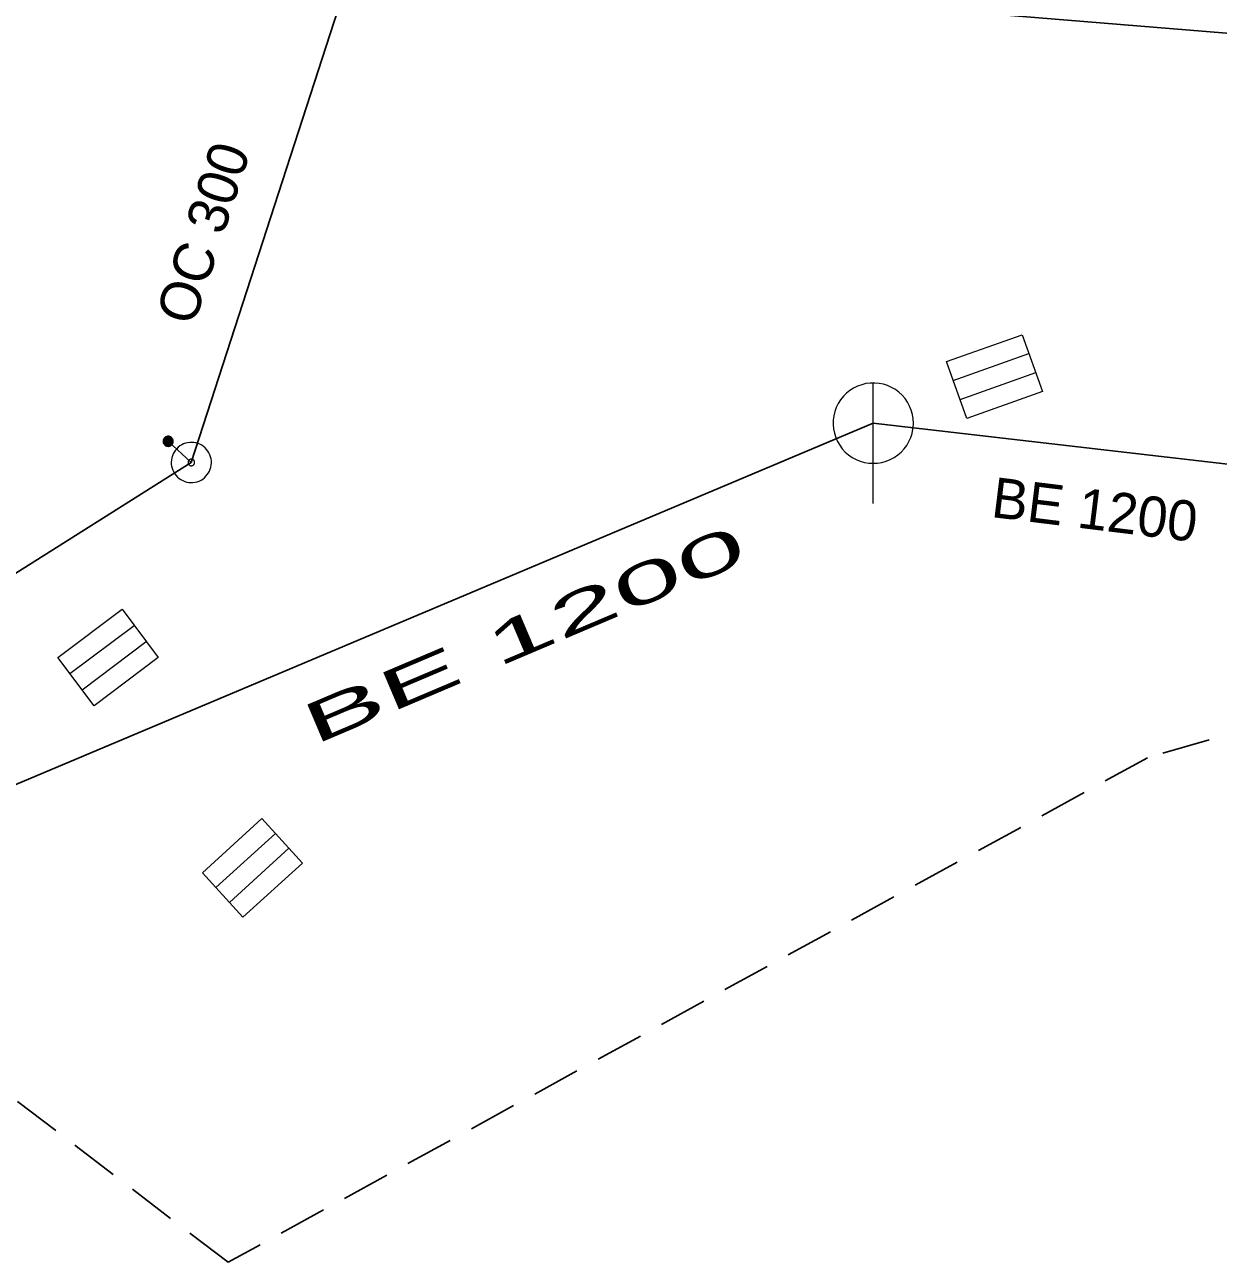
# Model space of a CAD drawing. Extents: x -725643 to -725418, y -978375 to -978221.
# Drawn here: x -725556.54 to -725526.82, y -978371.93 to -978341.11 of the extents above; entities that cross this region are included whole.
import ezdxf

# ---------------------------------------------------------------- set-up
doc = ezdxf.new("R2010")
doc.units = 0
doc.header["$LTSCALE"] = 0.4
doc.linetypes.add('MEDIUM_DASHED', pattern=[4.5, 3, -1.5])
doc.layers.add('1', color=7, linetype='Continuous')
for name, color, linetype, lineweight in [('14', 7, 'Continuous', 25), ('17', 7, 'Continuous', 25), ('22', 7, 'Continuous', 13), ('47', 7, 'Continuous', 13), ('63', 7, 'MEDIUM_DASHED', 25), ('9', 7, 'Continuous', 13)]:
    doc.layers.add(name, color=color, linetype=linetype, lineweight=lineweight)

msp = doc.modelspace()

# ---------------------------------------------------------------- linework, layer by layer
at = {"layer": '14'}
msp.add_line((-725535.414, -978351.036), (-725558.362, -978360.71), dxfattribs=at)
at = {"layer": '14', "lineweight": 13}
msp.add_line((-725552.39, -978352.015), (-725552.967, -978351.487), dxfattribs=at)
at = {"layer": '14'}
msp.add_lwpolyline([(-725503.472, -978351.493), (-725519.776, -978352.842), (-725535.414, -978351.036)], dxfattribs=at)
at = {"layer": '17'}
for p, q in [((-725548.553, -978340.172), (-725552.39, -978352.015)), ((-725552.39, -978352.015), (-725564.342, -978359.539))]:
    msp.add_line(p, q, dxfattribs=at)
msp.add_lwpolyline([(-725516.432, -978342.059), (-725524.989, -978341.46), (-725545.003, -978339.812), (-725548.553, -978340.172), (-725550.989, -978339.387)], dxfattribs=at)
at = {"layer": '22'}
for p, q in [((-725533.42, -978349.974), (-725531.536, -978349.303)), ((-725535.414, -978353.035), (-725535.413, -978350.035)), ((-725533.252, -978350.445), (-725531.368, -978349.775)), ((-725555.412, -978357.273), (-725553.813, -978356.071)), ((-725555.111, -978357.673), (-725553.513, -978356.471)), ((-725551.777, -978362.598), (-725550.298, -978361.252)), ((-725551.44, -978362.968), (-725549.961, -978361.622))]:
    msp.add_line(p, q, dxfattribs=at)
for points in [[(-725533.588, -978349.502), (-725531.703, -978348.832), (-725531.201, -978350.246), (-725533.085, -978350.916)], [(-725534.414, -978351.035), (-725534.419, -978350.926), (-725534.437, -978350.818), (-725534.467, -978350.712), (-725534.507, -978350.611), (-725534.559, -978350.514), (-725534.621, -978350.424), (-725534.693, -978350.341), (-725534.773, -978350.267), (-725534.861, -978350.201), (-725534.955, -978350.146), (-725535.055, -978350.101), (-725535.16, -978350.068), (-725535.267, -978350.046), (-725535.376, -978350.036), (-725535.486, -978350.038), (-725535.594, -978350.052), (-725535.701, -978350.077), (-725535.804, -978350.114), (-725535.902, -978350.163), (-725535.994, -978350.221), (-725536.08, -978350.29), (-725536.157, -978350.367), (-725536.226, -978350.453), (-725536.285, -978350.545), (-725536.333, -978350.643), (-725536.37, -978350.746), (-725536.396, -978350.853), (-725536.41, -978350.961), (-725536.413, -978351.071), (-725536.403, -978351.18), (-725536.382, -978351.287), (-725536.348, -978351.391), (-725536.304, -978351.491), (-725536.249, -978351.586), (-725536.183, -978351.674), (-725536.109, -978351.754), (-725536.026, -978351.826), (-725535.936, -978351.888), (-725535.84, -978351.94), (-725535.738, -978351.981), (-725535.633, -978352.011), (-725535.525, -978352.029), (-725535.415, -978352.035), (-725535.306, -978352.029), (-725535.198, -978352.011), (-725535.093, -978351.982), (-725534.991, -978351.941), (-725534.894, -978351.889), (-725534.804, -978351.827), (-725534.721, -978351.756), (-725534.646, -978351.676), (-725534.581, -978351.588), (-725534.525, -978351.494), (-725534.481, -978351.394), (-725534.447, -978351.29), (-725534.425, -978351.182), (-725534.415, -978351.073)], [(-725555.712, -978356.874), (-725554.114, -978355.671), (-725553.212, -978356.87), (-725554.81, -978358.072)], [(-725552.113, -978362.229), (-725550.635, -978360.882), (-725549.625, -978361.991), (-725551.104, -978363.338)]]:
    msp.add_lwpolyline(points, close=True, dxfattribs=at)
at = {"layer": '47'}
for points in [[(-725551.89, -978352.026), (-725551.891, -978351.974), (-725551.898, -978351.921), (-725551.911, -978351.871), (-725551.928, -978351.822), (-725551.951, -978351.774), (-725551.979, -978351.73), (-725552.011, -978351.689), (-725552.047, -978351.651), (-725552.087, -978351.617), (-725552.13, -978351.587), (-725552.176, -978351.562), (-725552.225, -978351.543), (-725552.275, -978351.528), (-725552.326, -978351.519), (-725552.378, -978351.515), (-725552.43, -978351.516), (-725552.483, -978351.523), (-725552.534, -978351.536), (-725552.582, -978351.553), (-725552.63, -978351.576), (-725552.674, -978351.604), (-725552.716, -978351.636), (-725552.754, -978351.672), (-725552.788, -978351.712), (-725552.817, -978351.755), (-725552.842, -978351.801), (-725552.862, -978351.85), (-725552.876, -978351.9), (-725552.885, -978351.951), (-725552.889, -978352.003), (-725552.888, -978352.055), (-725552.881, -978352.108), (-725552.869, -978352.159), (-725552.851, -978352.207), (-725552.828, -978352.255), (-725552.801, -978352.299), (-725552.769, -978352.341), (-725552.733, -978352.379), (-725552.692, -978352.413), (-725552.649, -978352.442), (-725552.603, -978352.467), (-725552.555, -978352.487), (-725552.504, -978352.501), (-725552.453, -978352.51), (-725552.401, -978352.514), (-725552.349, -978352.513), (-725552.296, -978352.506), (-725552.246, -978352.494), (-725552.197, -978352.476), (-725552.149, -978352.453), (-725552.105, -978352.426), (-725552.064, -978352.394), (-725552.026, -978352.358), (-725551.992, -978352.317), (-725551.962, -978352.274), (-725551.937, -978352.228), (-725551.918, -978352.18), (-725551.903, -978352.129), (-725551.894, -978352.078)], [(-725552.308, -978352.016), (-725552.307, -978352.007), (-725552.309, -978351.999), (-725552.311, -978351.991), (-725552.314, -978351.983), (-725552.318, -978351.975), (-725552.322, -978351.968), (-725552.327, -978351.961), (-725552.333, -978351.955), (-725552.34, -978351.95), (-725552.347, -978351.944), (-725552.355, -978351.94), (-725552.363, -978351.937), (-725552.371, -978351.935), (-725552.379, -978351.933), (-725552.388, -978351.933), (-725552.397, -978351.932), (-725552.405, -978351.934), (-725552.413, -978351.936), (-725552.421, -978351.939), (-725552.429, -978351.943), (-725552.436, -978351.947), (-725552.443, -978351.952), (-725552.449, -978351.958), (-725552.455, -978351.965), (-725552.46, -978351.972), (-725552.464, -978351.98), (-725552.467, -978351.988), (-725552.469, -978351.996), (-725552.471, -978352.004), (-725552.471, -978352.013), (-725552.472, -978352.022), (-725552.47, -978352.03), (-725552.468, -978352.038), (-725552.465, -978352.046), (-725552.461, -978352.054), (-725552.458, -978352.061), (-725552.452, -978352.068), (-725552.446, -978352.074), (-725552.439, -978352.08), (-725552.432, -978352.085), (-725552.424, -978352.089), (-725552.416, -978352.092), (-725552.408, -978352.094), (-725552.4, -978352.096), (-725552.391, -978352.096), (-725552.382, -978352.097), (-725552.374, -978352.095), (-725552.366, -978352.093), (-725552.358, -978352.09), (-725552.35, -978352.086), (-725552.343, -978352.083), (-725552.336, -978352.077), (-725552.33, -978352.071), (-725552.325, -978352.064), (-725552.319, -978352.057), (-725552.315, -978352.049), (-725552.312, -978352.041), (-725552.31, -978352.033), (-725552.308, -978352.025)]]:
    msp.add_lwpolyline(points, close=True, dxfattribs=at)
at = {"layer": '63'}
msp.add_lwpolyline([(-725440.663, -978348.762), (-725504.582, -978352.39), (-725504.582, -978352.39), (-725528.587, -978359.368), (-725528.587, -978359.368), (-725551.474, -978371.929), (-725551.474, -978371.929), (-725566.826, -978360.206), (-725566.826, -978360.206), (-725557.894, -978328.944), (-725533.89, -978332.573), (-725533.89, -978332.573), (-725529.424, -978311.918), (-725529.424, -978311.918), (-725514.351, -978316.105), (-725514.351, -978316.105), (-725517.422, -978329.502), (-725517.422, -978329.502), (-725504.582, -978332.573), (-725504.582, -978332.573), (-725495.092, -978321.408)], dxfattribs=at)
at = {"layer": '9'}
for points in [[(-725553.093, -978351.487), (-725553.093, -978351.5), (-725553.09, -978351.513), (-725553.088, -978351.526), (-725553.083, -978351.538), (-725553.076, -978351.55), (-725553.07, -978351.561), (-725553.061, -978351.571), (-725553.051, -978351.581), (-725553.041, -978351.589), (-725553.031, -978351.596), (-725553.019, -978351.602), (-725553.007, -978351.607), (-725552.994, -978351.61), (-725552.98, -978351.612), (-725552.968, -978351.614), (-725552.955, -978351.613), (-725552.941, -978351.611), (-725552.929, -978351.608), (-725552.916, -978351.603), (-725552.904, -978351.597), (-725552.894, -978351.59), (-725552.884, -978351.582), (-725552.874, -978351.572), (-725552.865, -978351.562), (-725552.858, -978351.551), (-725552.853, -978351.539), (-725552.848, -978351.527), (-725552.845, -978351.514), (-725552.843, -978351.501), (-725552.84, -978351.488), (-725552.842, -978351.475), (-725552.843, -978351.462), (-725552.847, -978351.449), (-725552.852, -978351.437), (-725552.857, -978351.425), (-725552.865, -978351.414), (-725552.872, -978351.404), (-725552.882, -978351.394), (-725552.892, -978351.386), (-725552.904, -978351.379), (-725552.916, -978351.373), (-725552.928, -978351.368), (-725552.941, -978351.365), (-725552.953, -978351.363), (-725552.967, -978351.362), (-725552.98, -978351.362), (-725552.992, -978351.364), (-725553.005, -978351.367), (-725553.017, -978351.372), (-725553.029, -978351.378), (-725553.041, -978351.385), (-725553.051, -978351.393), (-725553.061, -978351.403), (-725553.068, -978351.413), (-725553.076, -978351.424), (-725553.081, -978351.436), (-725553.087, -978351.448), (-725553.09, -978351.461), (-725553.092, -978351.474)], [(-725553.073, -978351.487), (-725553.073, -978351.498), (-725553.071, -978351.509), (-725553.068, -978351.52), (-725553.065, -978351.53), (-725553.059, -978351.54), (-725553.054, -978351.549), (-725553.046, -978351.558), (-725553.039, -978351.566), (-725553.029, -978351.573), (-725553.021, -978351.579), (-725553.011, -978351.584), (-725553, -978351.588), (-725552.99, -978351.591), (-725552.978, -978351.594), (-725552.968, -978351.594), (-725552.956, -978351.594), (-725552.946, -978351.592), (-725552.934, -978351.589), (-725552.924, -978351.585), (-725552.914, -978351.58), (-725552.906, -978351.574), (-725552.897, -978351.567), (-725552.889, -978351.559), (-725552.882, -978351.55), (-725552.875, -978351.541), (-725552.87, -978351.531), (-725552.867, -978351.521), (-725552.864, -978351.51), (-725552.862, -978351.499), (-725552.86, -978351.488), (-725552.86, -978351.477), (-725552.862, -978351.466), (-725552.865, -978351.455), (-725552.87, -978351.445), (-725552.875, -978351.435), (-725552.88, -978351.426), (-725552.887, -978351.417), (-725552.896, -978351.409), (-725552.904, -978351.402), (-725552.914, -978351.396), (-725552.924, -978351.391), (-725552.933, -978351.387), (-725552.945, -978351.384), (-725552.955, -978351.382), (-725552.967, -978351.382), (-725552.978, -978351.381), (-725552.989, -978351.383), (-725553, -978351.386), (-725553.009, -978351.39), (-725553.019, -978351.395), (-725553.029, -978351.401), (-725553.038, -978351.408), (-725553.046, -978351.416), (-725553.053, -978351.425), (-725553.058, -978351.434), (-725553.063, -978351.444), (-725553.068, -978351.454), (-725553.071, -978351.465), (-725553.073, -978351.476)], [(-725553.054, -978351.487), (-725553.054, -978351.496), (-725553.053, -978351.505), (-725553.049, -978351.514), (-725553.046, -978351.522), (-725553.043, -978351.53), (-725553.038, -978351.538), (-725553.031, -978351.545), (-725553.026, -978351.551), (-725553.019, -978351.557), (-725553.011, -978351.562), (-725553.002, -978351.566), (-725552.995, -978351.569), (-725552.985, -978351.572), (-725552.977, -978351.573), (-725552.968, -978351.575), (-725552.958, -978351.574), (-725552.95, -978351.573), (-725552.941, -978351.57), (-725552.933, -978351.567), (-725552.924, -978351.563), (-725552.916, -978351.558), (-725552.909, -978351.552), (-725552.904, -978351.546), (-725552.897, -978351.539), (-725552.892, -978351.531), (-725552.889, -978351.523), (-725552.886, -978351.515), (-725552.882, -978351.506), (-725552.882, -978351.497), (-725552.879, -978351.488), (-725552.88, -978351.479), (-725552.882, -978351.47), (-725552.884, -978351.461), (-725552.887, -978351.453), (-725552.892, -978351.445), (-725552.897, -978351.437), (-725552.902, -978351.43), (-725552.909, -978351.424), (-725552.916, -978351.418), (-725552.924, -978351.413), (-725552.931, -978351.409), (-725552.94, -978351.406), (-725552.948, -978351.403), (-725552.958, -978351.402), (-725552.967, -978351.401), (-725552.975, -978351.401), (-725552.985, -978351.402), (-725552.994, -978351.405), (-725553.002, -978351.408), (-725553.009, -978351.412), (-725553.017, -978351.417), (-725553.024, -978351.423), (-725553.031, -978351.429), (-725553.036, -978351.436), (-725553.041, -978351.444), (-725553.046, -978351.452), (-725553.049, -978351.46), (-725553.051, -978351.469), (-725553.053, -978351.478)], [(-725553.034, -978351.487), (-725553.034, -978351.494), (-725553.032, -978351.501), (-725553.031, -978351.508), (-725553.029, -978351.514), (-725553.026, -978351.52), (-725553.022, -978351.526), (-725553.017, -978351.532), (-725553.012, -978351.537), (-725553.007, -978351.541), (-725553, -978351.545), (-725552.995, -978351.548), (-725552.989, -978351.551), (-725552.982, -978351.552), (-725552.975, -978351.555), (-725552.968, -978351.555), (-725552.96, -978351.555), (-725552.953, -978351.553), (-725552.946, -978351.552), (-725552.941, -978351.549), (-725552.933, -978351.546), (-725552.929, -978351.542), (-725552.923, -978351.538), (-725552.918, -978351.533), (-725552.914, -978351.527), (-725552.909, -978351.521), (-725552.906, -978351.515), (-725552.904, -978351.509), (-725552.902, -978351.502), (-725552.901, -978351.495), (-725552.899, -978351.488), (-725552.899, -978351.481), (-725552.901, -978351.474), (-725552.902, -978351.467), (-725552.906, -978351.461), (-725552.909, -978351.454), (-725552.913, -978351.449), (-725552.916, -978351.443), (-725552.921, -978351.438), (-725552.928, -978351.434), (-725552.933, -978351.43), (-725552.94, -978351.427), (-725552.946, -978351.424), (-725552.953, -978351.422), (-725552.96, -978351.421), (-725552.967, -978351.421), (-725552.973, -978351.421), (-725552.98, -978351.421), (-725552.987, -978351.423), (-725552.994, -978351.426), (-725553, -978351.429), (-725553.005, -978351.433), (-725553.012, -978351.437), (-725553.017, -978351.442), (-725553.021, -978351.448), (-725553.024, -978351.453), (-725553.027, -978351.46), (-725553.031, -978351.466), (-725553.031, -978351.473), (-725553.034, -978351.48)], [(-725553.014, -978351.487), (-725553.014, -978351.492), (-725553.014, -978351.497), (-725553.012, -978351.502), (-725553.011, -978351.506), (-725553.009, -978351.511), (-725553.005, -978351.515), (-725553.002, -978351.518), (-725552.999, -978351.522), (-725552.995, -978351.525), (-725552.992, -978351.528), (-725552.987, -978351.53), (-725552.982, -978351.532), (-725552.978, -978351.533), (-725552.973, -978351.535), (-725552.968, -978351.535), (-725552.963, -978351.535), (-725552.958, -978351.534), (-725552.953, -978351.533), (-725552.948, -978351.531), (-725552.943, -978351.529), (-725552.94, -978351.526), (-725552.936, -978351.523), (-725552.933, -978351.519), (-725552.929, -978351.516), (-725552.926, -978351.512), (-725552.924, -978351.507), (-725552.923, -978351.503), (-725552.921, -978351.498), (-725552.921, -978351.493), (-725552.919, -978351.488), (-725552.919, -978351.483), (-725552.921, -978351.478), (-725552.921, -978351.473), (-725552.924, -978351.469), (-725552.926, -978351.464), (-725552.929, -978351.46), (-725552.931, -978351.456), (-725552.934, -978351.453), (-725552.938, -978351.45), (-725552.943, -978351.447), (-725552.948, -978351.445), (-725552.951, -978351.443), (-725552.956, -978351.442), (-725552.962, -978351.441), (-725552.967, -978351.441), (-725552.972, -978351.441), (-725552.977, -978351.442), (-725552.982, -978351.442), (-725552.985, -978351.444), (-725552.99, -978351.446), (-725552.995, -978351.449), (-725552.997, -978351.452), (-725553.002, -978351.455), (-725553.004, -978351.459), (-725553.007, -978351.463), (-725553.009, -978351.468), (-725553.012, -978351.472), (-725553.012, -978351.477), (-725553.014, -978351.482)], [(-725552.994, -978351.487), (-725552.994, -978351.49), (-725552.995, -978351.493), (-725552.994, -978351.495), (-725552.992, -978351.498), (-725552.992, -978351.501), (-725552.99, -978351.503), (-725552.987, -978351.505), (-725552.985, -978351.507), (-725552.983, -978351.509), (-725552.982, -978351.511), (-725552.978, -978351.513), (-725552.975, -978351.514), (-725552.973, -978351.514), (-725552.97, -978351.515), (-725552.968, -978351.515), (-725552.965, -978351.515), (-725552.962, -978351.515), (-725552.958, -978351.514), (-725552.956, -978351.513), (-725552.953, -978351.512), (-725552.951, -978351.51), (-725552.948, -978351.508), (-725552.946, -978351.506), (-725552.946, -978351.504), (-725552.943, -978351.502), (-725552.943, -978351.499), (-725552.941, -978351.496), (-725552.941, -978351.494), (-725552.94, -978351.491), (-725552.938, -978351.488), (-725552.94, -978351.485), (-725552.94, -978351.482), (-725552.941, -978351.479), (-725552.941, -978351.477), (-725552.943, -978351.474), (-725552.945, -978351.472), (-725552.946, -978351.469), (-725552.948, -978351.467), (-725552.951, -978351.466), (-725552.953, -978351.464), (-725552.955, -978351.463), (-725552.958, -978351.462), (-725552.96, -978351.461), (-725552.963, -978351.461), (-725552.967, -978351.46), (-725552.97, -978351.461), (-725552.973, -978351.46), (-725552.975, -978351.462), (-725552.978, -978351.462), (-725552.98, -978351.463), (-725552.982, -978351.465), (-725552.985, -978351.466), (-725552.987, -978351.468), (-725552.989, -978351.471), (-725552.99, -978351.473), (-725552.992, -978351.476), (-725552.992, -978351.478), (-725552.994, -978351.481), (-725552.994, -978351.484)], [(-725552.975, -978351.487), (-725552.975, -978351.489), (-725552.975, -978351.489), (-725552.973, -978351.489), (-725552.973, -978351.491), (-725552.975, -978351.492), (-725552.973, -978351.492), (-725552.973, -978351.492), (-725552.973, -978351.494), (-725552.973, -978351.494), (-725552.972, -978351.495), (-725552.97, -978351.495), (-725552.97, -978351.495), (-725552.97, -978351.496), (-725552.968, -978351.496), (-725552.968, -978351.496), (-725552.967, -978351.496), (-725552.965, -978351.496), (-725552.965, -978351.495), (-725552.965, -978351.495), (-725552.963, -978351.495), (-725552.963, -978351.494), (-725552.963, -978351.494), (-725552.962, -978351.493), (-725552.962, -978351.493), (-725552.96, -978351.492), (-725552.96, -978351.491), (-725552.958, -978351.49), (-725552.958, -978351.49), (-725552.958, -978351.489), (-725552.958, -978351.488), (-725552.958, -978351.487), (-725552.958, -978351.486), (-725552.958, -978351.486), (-725552.96, -978351.485), (-725552.96, -978351.484), (-725552.96, -978351.483), (-725552.96, -978351.483), (-725552.962, -978351.482), (-725552.962, -978351.482), (-725552.963, -978351.481), (-725552.963, -978351.481), (-725552.965, -978351.48), (-725552.965, -978351.48), (-725552.965, -978351.48), (-725552.967, -978351.48), (-725552.968, -978351.48), (-725552.968, -978351.48), (-725552.968, -978351.48), (-725552.97, -978351.481), (-725552.97, -978351.48), (-725552.972, -978351.482), (-725552.972, -978351.482), (-725552.973, -978351.482), (-725552.973, -978351.482), (-725552.973, -978351.484), (-725552.973, -978351.485), (-725552.973, -978351.486), (-725552.975, -978351.486), (-725552.975, -978351.487)]]:
    msp.add_lwpolyline(points, close=True, dxfattribs=at)

# ---------------------------------------------------------------- texts
at = {"layer": '1'}
for s, rotation, p in [('OC 300', 72, (-725552.333, -978348.644)), ('BE 1200 ', 353, (-725532.502, -978353.37))]:
    msp.add_text(s, height=1, rotation=rotation, dxfattribs=at).set_placement(p)
at = {"layer": '1', "width": 2.3}
msp.add_text('BE 1200 ', height=1, rotation=23, dxfattribs=at).set_placement((-725549.341, -978359.061))

doc.saveas('drawing.dxf')
